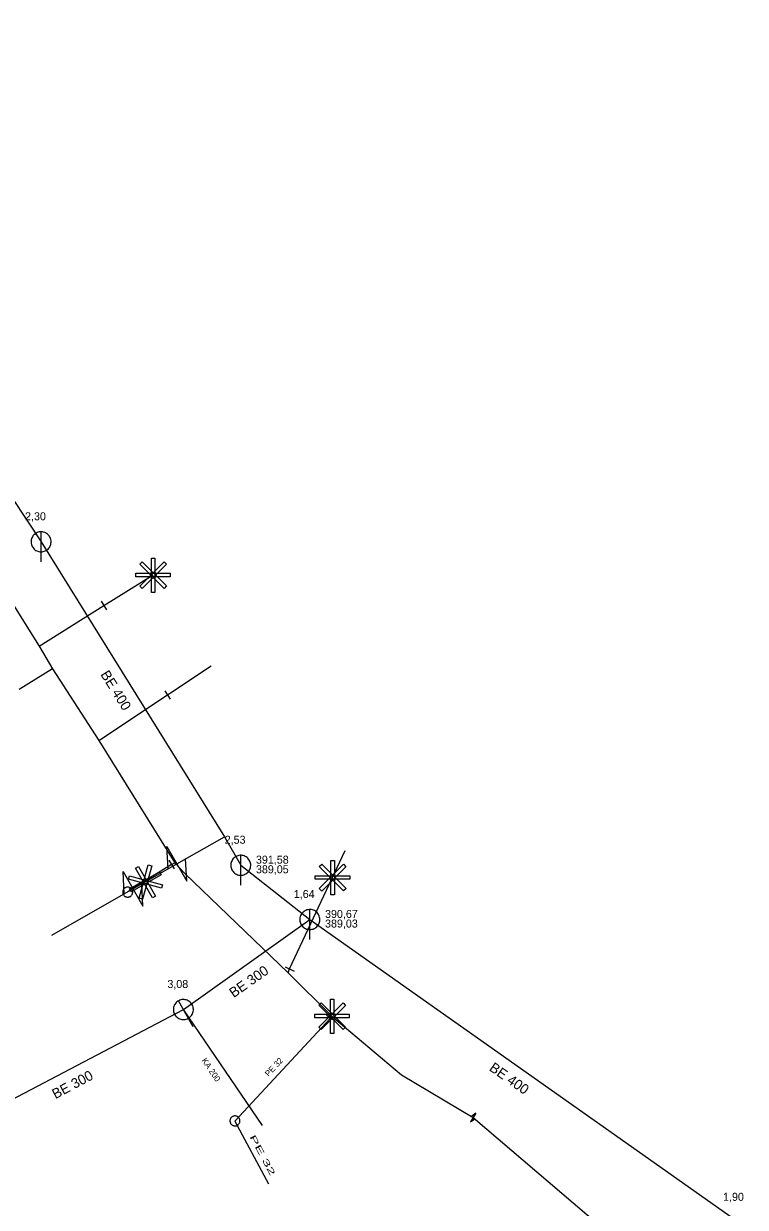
# Model space of a CAD drawing. Extents: x -809028 to -807737, y -990545 to -989489.
# Drawn here: x -808495.3 to -808423.2, y -990079 to -989960.8 of the extents above; entities that cross this region are included whole.
import ezdxf

# ---------------------------------------------------------------- set-up
doc = ezdxf.new("R2010")
doc.units = 0
doc.header["$LTSCALE"] = 0.32
for name, color, linetype, lineweight in [('1', 7, 'Continuous', 13), ('10', 7, 'Continuous', 13), ('11', 7, 'Continuous', 13), ('12', 7, 'Continuous', 13), ('13', 7, 'Continuous', 13), ('14', 7, 'Continuous', 25), ('17', 7, 'Continuous', 25), ('22', 7, 'Continuous', 13), ('23', 7, 'Continuous', 13), ('31', 7, 'Continuous', 13), ('34', 7, 'Continuous', 13), ('47', 7, 'Continuous', 13)]:
    doc.layers.add(name, color=color, linetype=linetype, lineweight=lineweight)

msp = doc.modelspace()

# ---------------------------------------------------------------- linework, layer by layer
at = {"layer": '10'}
for points in [[(-808482.865, -990044.827), (-808482.526, -990044.92), (-808483.432, -990048.233), (-808483.77, -990048.14)], [(-808484.847, -990046.234), (-808484.756, -990045.896), (-808481.442, -990046.802), (-808481.534, -990047.14)], [(-808481.76, -990045.516), (-808481.587, -990045.82), (-808484.57, -990047.522), (-808484.744, -990047.218)], [(-808484.145, -990045.139), (-808483.841, -990044.965), (-808482.138, -990047.949), (-808482.442, -990048.122)]]:
    msp.add_lwpolyline(points, close=True, dxfattribs=at)
at = {"layer": '11'}
for p, q in [((-808492.491, -990051.84), (-808484.394, -990047.221)), ((-808471.464, -990070.871), (-808479.357, -990059.274))]:
    msp.add_line(p, q, dxfattribs=at)
msp.add_lwpolyline([(-808484.394, -990047.221), (-808480.011, -990044.72), (-808475.248, -990042.026)], dxfattribs=at)
at = {"layer": '12'}
for points in [[(-808481.293, -990014.527), (-808481.044, -990014.775), (-808483.473, -990017.204), (-808483.72, -990016.956)], [(-808483.712, -990014.766), (-808483.465, -990014.518), (-808481.036, -990016.947), (-808481.282, -990017.195)], [(-808482.559, -990014.163), (-808482.208, -990014.163), (-808482.208, -990017.598), (-808482.559, -990017.598)], [(-808480.674, -990015.672), (-808480.674, -990016.022), (-808484.11, -990016.022), (-808484.11, -990015.672)], [(-808463.358, -990044.755), (-808463.11, -990045.003), (-808465.539, -990047.432), (-808465.786, -990047.184)], [(-808465.777, -990044.994), (-808465.53, -990044.746), (-808463.101, -990047.175), (-808463.348, -990047.423)], [(-808464.624, -990044.391), (-808464.274, -990044.391), (-808464.274, -990047.826), (-808464.624, -990047.826)], [(-808462.74, -990045.9), (-808462.74, -990046.25), (-808466.175, -990046.25), (-808466.175, -990045.9)], [(-808463.405, -990058.606), (-808463.157, -990058.854), (-808465.586, -990061.283), (-808465.833, -990061.035)], [(-808465.824, -990058.845), (-808465.577, -990058.597), (-808463.148, -990061.026), (-808463.395, -990061.274)], [(-808464.671, -990058.242), (-808464.321, -990058.242), (-808464.321, -990061.677), (-808464.671, -990061.677)], [(-808462.787, -990059.751), (-808462.787, -990060.101), (-808466.222, -990060.101), (-808466.222, -990059.751)]]:
    msp.add_lwpolyline(points, close=True, dxfattribs=at)
at = {"layer": '13'}
for p, q in [((-808487.301, -990018.903), (-808482.381, -990015.833)), ((-808493.783, -990022.945), (-808487.301, -990018.903)), ((-808492.427, -990025.232), (-808495.776, -990027.289)), ((-808480.958, -990027.837), (-808476.585, -990024.932)), ((-808487.791, -990032.384), (-808480.958, -990027.837)), ((-808480.561, -990044.778), (-808484.918, -990047.51)), ((-808464.643, -990060.136), (-808474.204, -990070.436)), ((-808474.204, -990070.436), (-808470.864, -990076.682))]:
    msp.add_line(p, q, dxfattribs=at)
msp.add_lwpolyline([(-808468.886, -990055.611), (-808468.749, -990055.219), (-808463.203, -990043.379)], dxfattribs=at)
at = {"layer": '14'}
for p, q in [((-808511.252, -989985.91), (-808493.579, -990012.532)), ((-808479.357, -990059.274), (-808466.725, -990050.28)), ((-808501.469, -990070.893), (-808479.357, -990059.274))]:
    msp.add_line(p, q, dxfattribs=at)
at = {"layer": '14', "lineweight": 13}
for p, q in [((-808480.561, -990044.778), (-808480.228, -990044.603)), ((-808464.513, -990059.927), (-808464.643, -990060.136))]:
    msp.add_line(p, q, dxfattribs=at)
at = {"layer": '14'}
for points in [[(-808493.579, -990012.532), (-808475.248, -990042.026), (-808473.629, -990044.855)], [(-808473.629, -990044.855), (-808466.725, -990050.28), (-808423.829, -990080.539)]]:
    msp.add_lwpolyline(points, dxfattribs=at)
at = {"layer": '17'}
for points in [[(-808533.093, -989960.754), (-808523.558, -989975.626), (-808520.82, -989979.929), (-808519.804, -989981.686), (-808508.475, -989999.488), (-808507.335, -990001.35), (-808493.783, -990022.945), (-808492.427, -990025.232), (-808487.791, -990032.384), (-808480.228, -990044.603), (-808479.217, -990045.69), (-808468.886, -990055.611), (-808464.513, -990059.927), (-808457.57, -990065.789), (-808450.392, -990070.058)], [(-808450.392, -990070.058), (-808407.697, -990106.489), (-808400.245, -990114.046), (-808383.377, -990131.011), (-808376.145, -990135.581), (-808355.548, -990147.837), (-808349.357, -990154.173), (-808344.447, -990167.226), (-808345.032, -990197.443), (-808345.713, -990210.651)]]:
    msp.add_lwpolyline(points, dxfattribs=at)
at = {"layer": '22'}
for p, q in [((-808493.579, -990014.532), (-808493.578, -990011.532)), ((-808473.629, -990046.855), (-808473.628, -990043.855)), ((-808466.725, -990052.28), (-808466.724, -990049.28)), ((-808478.37, -990061.014), (-808479.849, -990058.404))]:
    msp.add_line(p, q, dxfattribs=at)
for points in [[(-808492.579, -990012.532), (-808492.584, -990012.423), (-808492.602, -990012.315), (-808492.632, -990012.209), (-808492.672, -990012.108), (-808492.724, -990012.011), (-808492.786, -990011.921), (-808492.858, -990011.838), (-808492.938, -990011.764), (-808493.026, -990011.698), (-808493.12, -990011.643), (-808493.22, -990011.598), (-808493.325, -990011.565), (-808493.432, -990011.543), (-808493.541, -990011.533), (-808493.651, -990011.535), (-808493.759, -990011.549), (-808493.866, -990011.574), (-808493.969, -990011.611), (-808494.067, -990011.66), (-808494.159, -990011.718), (-808494.245, -990011.787), (-808494.322, -990011.864), (-808494.391, -990011.95), (-808494.45, -990012.042), (-808494.498, -990012.14), (-808494.535, -990012.243), (-808494.561, -990012.35), (-808494.575, -990012.458), (-808494.578, -990012.568), (-808494.568, -990012.677), (-808494.547, -990012.784), (-808494.513, -990012.888), (-808494.469, -990012.988), (-808494.414, -990013.083), (-808494.348, -990013.171), (-808494.274, -990013.251), (-808494.191, -990013.323), (-808494.101, -990013.385), (-808494.005, -990013.437), (-808493.903, -990013.478), (-808493.798, -990013.508), (-808493.69, -990013.526), (-808493.58, -990013.532), (-808493.471, -990013.526), (-808493.363, -990013.508), (-808493.258, -990013.479), (-808493.156, -990013.438), (-808493.059, -990013.386), (-808492.969, -990013.324), (-808492.886, -990013.253), (-808492.811, -990013.173), (-808492.746, -990013.085), (-808492.69, -990012.991), (-808492.646, -990012.891), (-808492.612, -990012.787), (-808492.59, -990012.679), (-808492.58, -990012.57)], [(-808472.629, -990044.855), (-808472.634, -990044.746), (-808472.652, -990044.638), (-808472.682, -990044.532), (-808472.722, -990044.431), (-808472.774, -990044.334), (-808472.836, -990044.244), (-808472.908, -990044.161), (-808472.988, -990044.087), (-808473.076, -990044.021), (-808473.17, -990043.966), (-808473.27, -990043.921), (-808473.375, -990043.888), (-808473.482, -990043.866), (-808473.591, -990043.856), (-808473.701, -990043.858), (-808473.809, -990043.872), (-808473.916, -990043.897), (-808474.019, -990043.934), (-808474.117, -990043.983), (-808474.209, -990044.041), (-808474.295, -990044.11), (-808474.372, -990044.187), (-808474.441, -990044.273), (-808474.5, -990044.365), (-808474.548, -990044.463), (-808474.585, -990044.566), (-808474.611, -990044.673), (-808474.625, -990044.781), (-808474.628, -990044.891), (-808474.618, -990045), (-808474.597, -990045.107), (-808474.563, -990045.211), (-808474.519, -990045.311), (-808474.464, -990045.406), (-808474.398, -990045.494), (-808474.324, -990045.574), (-808474.241, -990045.646), (-808474.151, -990045.708), (-808474.055, -990045.76), (-808473.953, -990045.801), (-808473.848, -990045.831), (-808473.74, -990045.849), (-808473.63, -990045.855), (-808473.521, -990045.849), (-808473.413, -990045.831), (-808473.308, -990045.802), (-808473.206, -990045.761), (-808473.109, -990045.709), (-808473.019, -990045.647), (-808472.936, -990045.576), (-808472.861, -990045.496), (-808472.796, -990045.408), (-808472.74, -990045.314), (-808472.696, -990045.214), (-808472.662, -990045.11), (-808472.64, -990045.002), (-808472.63, -990044.893)], [(-808465.725, -990050.28), (-808465.73, -990050.171), (-808465.748, -990050.063), (-808465.778, -990049.957), (-808465.818, -990049.856), (-808465.87, -990049.759), (-808465.932, -990049.669), (-808466.004, -990049.586), (-808466.084, -990049.512), (-808466.172, -990049.446), (-808466.266, -990049.391), (-808466.366, -990049.346), (-808466.471, -990049.313), (-808466.578, -990049.291), (-808466.687, -990049.281), (-808466.797, -990049.283), (-808466.905, -990049.297), (-808467.012, -990049.322), (-808467.115, -990049.359), (-808467.213, -990049.408), (-808467.305, -990049.466), (-808467.391, -990049.535), (-808467.468, -990049.612), (-808467.537, -990049.698), (-808467.596, -990049.79), (-808467.644, -990049.888), (-808467.681, -990049.991), (-808467.707, -990050.098), (-808467.721, -990050.206), (-808467.724, -990050.316), (-808467.714, -990050.425), (-808467.693, -990050.532), (-808467.659, -990050.636), (-808467.615, -990050.736), (-808467.56, -990050.831), (-808467.494, -990050.919), (-808467.42, -990050.999), (-808467.337, -990051.071), (-808467.247, -990051.133), (-808467.151, -990051.185), (-808467.049, -990051.226), (-808466.944, -990051.256), (-808466.836, -990051.274), (-808466.726, -990051.28), (-808466.617, -990051.274), (-808466.509, -990051.256), (-808466.404, -990051.227), (-808466.302, -990051.186), (-808466.205, -990051.134), (-808466.115, -990051.072), (-808466.032, -990051.001), (-808465.957, -990050.921), (-808465.892, -990050.833), (-808465.836, -990050.739), (-808465.792, -990050.639), (-808465.758, -990050.535), (-808465.736, -990050.427), (-808465.726, -990050.318)], [(-808478.486, -990058.781), (-808478.545, -990058.689), (-808478.614, -990058.604), (-808478.693, -990058.526), (-808478.777, -990058.458), (-808478.87, -990058.4), (-808478.969, -990058.352), (-808479.072, -990058.315), (-808479.178, -990058.29), (-808479.287, -990058.276), (-808479.396, -990058.275), (-808479.505, -990058.285), (-808479.613, -990058.308), (-808479.717, -990058.342), (-808479.817, -990058.387), (-808479.911, -990058.443), (-808479.999, -990058.508), (-808480.079, -990058.583), (-808480.151, -990058.666), (-808480.212, -990058.757), (-808480.263, -990058.852), (-808480.304, -990058.955), (-808480.333, -990059.06), (-808480.351, -990059.169), (-808480.356, -990059.278), (-808480.35, -990059.387), (-808480.331, -990059.495), (-808480.301, -990059.6), (-808480.26, -990059.701), (-808480.208, -990059.798), (-808480.145, -990059.888), (-808480.074, -990059.971), (-808479.993, -990060.044), (-808479.906, -990060.11), (-808479.811, -990060.165), (-808479.71, -990060.209), (-808479.606, -990060.242), (-808479.499, -990060.264), (-808479.39, -990060.273), (-808479.28, -990060.271), (-808479.172, -990060.257), (-808479.065, -990060.231), (-808478.963, -990060.193), (-808478.864, -990060.144), (-808478.772, -990060.085), (-808478.687, -990060.016), (-808478.61, -990059.939), (-808478.541, -990059.853), (-808478.483, -990059.76), (-808478.435, -990059.662), (-808478.398, -990059.559), (-808478.372, -990059.453), (-808478.359, -990059.344), (-808478.357, -990059.235), (-808478.368, -990059.126), (-808478.389, -990059.019), (-808478.423, -990058.914), (-808478.468, -990058.814)]]:
    msp.add_lwpolyline(points, close=True, dxfattribs=at)
at = {"layer": '23'}
for points in [[(-808484.504, -990047.271), (-808484.535, -990047.228), (-808484.57, -990047.188), (-808484.609, -990047.155), (-808484.651, -990047.123), (-808484.696, -990047.097), (-808484.744, -990047.076), (-808484.794, -990047.059), (-808484.844, -990047.049), (-808484.896, -990047.042), (-808484.949, -990047.042), (-808485.001, -990047.047), (-808485.053, -990047.058), (-808485.102, -990047.074), (-808485.149, -990047.095), (-808485.195, -990047.12), (-808485.239, -990047.152), (-808485.277, -990047.185), (-808485.313, -990047.226), (-808485.343, -990047.266), (-808485.37, -990047.311), (-808485.391, -990047.361), (-808485.407, -990047.41), (-808485.418, -990047.462), (-808485.425, -990047.513), (-808485.425, -990047.565), (-808485.419, -990047.618), (-808485.408, -990047.668), (-808485.392, -990047.718), (-808485.371, -990047.766), (-808485.345, -990047.811), (-808485.315, -990047.854), (-808485.28, -990047.893), (-808485.241, -990047.929), (-808485.199, -990047.96), (-808485.154, -990047.984), (-808485.106, -990048.006), (-808485.057, -990048.023), (-808485.005, -990048.035), (-808484.953, -990048.04)], [(-808485.313, -990047.226), (-808485.343, -990047.266), (-808485.37, -990047.311), (-808485.391, -990047.361), (-808485.407, -990047.41), (-808485.418, -990047.462), (-808485.425, -990047.513), (-808485.425, -990047.565), (-808485.419, -990047.618), (-808485.408, -990047.668), (-808485.392, -990047.718), (-808485.371, -990047.766), (-808485.345, -990047.811), (-808485.315, -990047.854), (-808485.28, -990047.893), (-808485.241, -990047.929), (-808485.199, -990047.96), (-808485.154, -990047.984), (-808485.106, -990048.006), (-808485.057, -990048.023), (-808485.005, -990048.035), (-808484.953, -990048.04), (-808484.902, -990048.041), (-808484.849, -990048.035), (-808484.798, -990048.025), (-808484.748, -990048.008), (-808484.701, -990047.987), (-808484.655, -990047.962), (-808484.613, -990047.931), (-808484.573, -990047.896), (-808484.538, -990047.857), (-808484.508, -990047.815), (-808484.481, -990047.77), (-808484.459, -990047.723), (-808484.444, -990047.672), (-808484.431, -990047.622), (-808484.426, -990047.57), (-808484.425, -990047.517), (-808484.431, -990047.465), (-808484.442, -990047.414)], [(-808484.953, -990048.04), (-808484.902, -990048.041), (-808484.849, -990048.035), (-808484.798, -990048.025), (-808484.748, -990048.008), (-808484.701, -990047.987), (-808484.655, -990047.962), (-808484.613, -990047.931), (-808484.573, -990047.896), (-808484.538, -990047.857), (-808484.508, -990047.815), (-808484.481, -990047.77), (-808484.459, -990047.723), (-808484.444, -990047.672), (-808484.431, -990047.622), (-808484.426, -990047.57), (-808484.425, -990047.517), (-808484.431, -990047.465), (-808484.442, -990047.414), (-808484.459, -990047.364), (-808484.479, -990047.317), (-808484.504, -990047.271), (-808484.535, -990047.228), (-808484.57, -990047.188), (-808484.609, -990047.155), (-808484.651, -990047.123), (-808484.696, -990047.097), (-808484.744, -990047.076), (-808484.794, -990047.059), (-808484.844, -990047.049), (-808484.896, -990047.042), (-808484.949, -990047.042), (-808485.001, -990047.047), (-808485.053, -990047.058), (-808485.102, -990047.074), (-808485.149, -990047.095), (-808485.195, -990047.12), (-808485.239, -990047.152), (-808485.277, -990047.185), (-808485.313, -990047.226)], [(-808484.442, -990047.414), (-808484.459, -990047.364), (-808484.479, -990047.317), (-808484.504, -990047.271)], [(-808473.749, -990070.61), (-808473.73, -990070.564), (-808473.715, -990070.513), (-808473.708, -990070.46), (-808473.705, -990070.408), (-808473.707, -990070.355), (-808473.713, -990070.303), (-808473.727, -990070.254), (-808473.746, -990070.204), (-808473.769, -990070.158), (-808473.797, -990070.114), (-808473.83, -990070.073), (-808473.866, -990070.035), (-808473.906, -990070.002), (-808473.95, -990069.972), (-808473.997, -990069.948), (-808474.045, -990069.929), (-808474.095, -990069.916), (-808474.147, -990069.907), (-808474.199, -990069.903), (-808474.252, -990069.905), (-808474.303, -990069.913), (-808474.353, -990069.925), (-808474.403, -990069.945), (-808474.45, -990069.967), (-808474.494, -990069.996), (-808474.534, -990070.029), (-808474.572, -990070.064), (-808474.605, -990070.105), (-808474.634, -990070.148), (-808474.659, -990070.195), (-808474.677, -990070.244), (-808474.692, -990070.295), (-808474.701, -990070.345), (-808474.703, -990070.398), (-808474.702, -990070.45), (-808474.694, -990070.501), (-808474.681, -990070.553), (-808474.663, -990070.602), (-808474.639, -990070.649)], [(-808474.303, -990069.913), (-808474.353, -990069.925), (-808474.403, -990069.945), (-808474.45, -990069.967), (-808474.494, -990069.996), (-808474.534, -990070.029), (-808474.572, -990070.064), (-808474.605, -990070.105), (-808474.634, -990070.148), (-808474.659, -990070.195), (-808474.677, -990070.244), (-808474.692, -990070.295), (-808474.701, -990070.345), (-808474.703, -990070.398), (-808474.702, -990070.45), (-808474.694, -990070.501), (-808474.681, -990070.553), (-808474.663, -990070.602), (-808474.639, -990070.649), (-808474.611, -990070.692), (-808474.579, -990070.733), (-808474.543, -990070.771), (-808474.502, -990070.805), (-808474.458, -990070.834), (-808474.412, -990070.857), (-808474.364, -990070.877), (-808474.314, -990070.891), (-808474.261, -990070.899), (-808474.209, -990070.902), (-808474.158, -990070.9), (-808474.106, -990070.893), (-808474.055, -990070.88), (-808474.005, -990070.862), (-808473.958, -990070.838), (-808473.914, -990070.81), (-808473.874, -990070.778), (-808473.836, -990070.742), (-808473.802, -990070.7), (-808473.774, -990070.658), (-808473.749, -990070.61)], [(-808474.639, -990070.649), (-808474.611, -990070.692), (-808474.579, -990070.733), (-808474.543, -990070.771)], [(-808474.543, -990070.771), (-808474.502, -990070.805), (-808474.458, -990070.834), (-808474.412, -990070.857), (-808474.364, -990070.877), (-808474.314, -990070.891), (-808474.261, -990070.899), (-808474.209, -990070.902), (-808474.158, -990070.9), (-808474.106, -990070.893), (-808474.055, -990070.88), (-808474.005, -990070.862), (-808473.958, -990070.838), (-808473.914, -990070.81), (-808473.874, -990070.778), (-808473.836, -990070.742), (-808473.802, -990070.7), (-808473.774, -990070.658), (-808473.749, -990070.61), (-808473.73, -990070.564), (-808473.715, -990070.513), (-808473.708, -990070.46), (-808473.705, -990070.408), (-808473.707, -990070.355), (-808473.713, -990070.303), (-808473.727, -990070.254), (-808473.746, -990070.204), (-808473.769, -990070.158), (-808473.797, -990070.114), (-808473.83, -990070.073), (-808473.866, -990070.035), (-808473.906, -990070.002), (-808473.95, -990069.972), (-808473.997, -990069.948), (-808474.045, -990069.929), (-808474.095, -990069.916), (-808474.147, -990069.907), (-808474.199, -990069.903), (-808474.252, -990069.905), (-808474.303, -990069.913)]]:
    msp.add_lwpolyline(points, dxfattribs=at)
at = {"layer": '31'}
for points in [[(-808480.879, -990045.215), (-808481.001, -990042.983), (-808479.019, -990046.457), (-808479.142, -990044.224)], [(-808485.262, -990047.716), (-808485.384, -990045.484), (-808483.402, -990048.958), (-808483.525, -990046.725)]]:
    msp.add_lwpolyline(points, dxfattribs=at)
at = {"layer": '34'}
for p, q in [((-808487.565, -990018.478), (-808487.036, -990019.327)), ((-808481.222, -990027.412), (-808480.693, -990028.261)), ((-808480.827, -990044.354), (-808480.295, -990045.201)), ((-808469.201, -990055.007), (-808468.296, -990055.431)), ((-808464.217, -990060.399), (-808465.067, -990059.872))]:
    msp.add_line(p, q, dxfattribs=at)
at = {"layer": '47'}
msp.add_line((-808450.131, -990069.619), (-808450.541, -990069.924), dxfattribs=at)
msp.add_lwpolyline([(-808450.131, -990069.619), (-808450.652, -990070.496), (-808450.242, -990070.191)], dxfattribs=at)

# ---------------------------------------------------------------- texts
at = {"layer": '1'}
for s, p in [('2,30', (-808495.179, -990010.38)), ('2,53', (-808475.229, -990042.703)), ('1,64', (-808468.325, -990048.128)), ('3,08', (-808480.957, -990057.122)), ('1,90', (-808425.43, -990078.387))]:
    msp.add_text(s, height=0.8, dxfattribs=at).set_placement(p)
for s, height, rotation, p in [('BE 400', 1, 302, (-808487.683, -990025.778)), ('BE 300', 1, 35, (-808474.333, -990058.134)), ('KA 200', 0.6, 304, (-808477.573, -990064.367)), ('PE 32 ', 0.6, 47, (-808470.84, -990066.017)), ('BE 400', 1, 325, (-808448.873, -990065.302)), ('BE 300', 1, 28, (-808492.145, -990068.237))]:
    msp.add_text(s, height=height, rotation=rotation, dxfattribs=at).set_placement(p)
at = {"layer": '1', "width": 2.05}
msp.add_text('PE 32 ', height=0.6, rotation=298, dxfattribs=at).set_placement((-808472.763, -990071.981))
at = {"layer": '14'}
for s, p in [('391,58', (-808472.108, -990044.695)), ('389,05', (-808472.108, -990045.655)), ('390,67', (-808465.203, -990050.12)), ('389,03', (-808465.203, -990051.08))]:
    msp.add_text(s, height=0.8, dxfattribs=at).set_placement(p)

doc.saveas('drawing.dxf')
